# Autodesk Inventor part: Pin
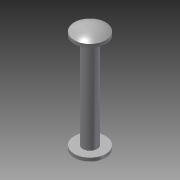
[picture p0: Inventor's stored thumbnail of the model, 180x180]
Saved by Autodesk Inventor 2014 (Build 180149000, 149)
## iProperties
Created: 2009-03
Part Number: Pin
Material: Steel
Document SubType Name: Modeling
Designer: tangg
Density: 7.85 g/cm^3
Appearance: Steel
Author: tangg
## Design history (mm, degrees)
sketch "Sketch1"
  geometry: C1 r 1.5 at (0, 0); 1 further point
  constraints: 1 centre point, 1 coincident
  dimensions: "d0" = 3 diameter of C1
extrude "Extrusion1" new body sketch "Sketch1" stored distance "d1" = 20; taper "d2" = 0 deg
sketch "Sketch2"
  geometry: L1 (1.5, -10)-(-1.5, -10) reference; L2 (0, -11.82)-(0, -10); L3 (-3.289, -10)-(0, -10); L4 (-3.289, -10)-(-3.289, -10.695); A1 r 5.373 centre (0, -6.447) between (-3.289, -10.695) and (0, -11.82); 1 further point
  constraints: 6 end point, 2 point on circle, 1 centre point, 1 collinear, 1 midpoint, 1 perpendicular
revolve "Revolution1" sketch "Sketch2" stored, may be unused: angle "d3" = 90 deg
mirror "Mirror1"
body "Solid1"
